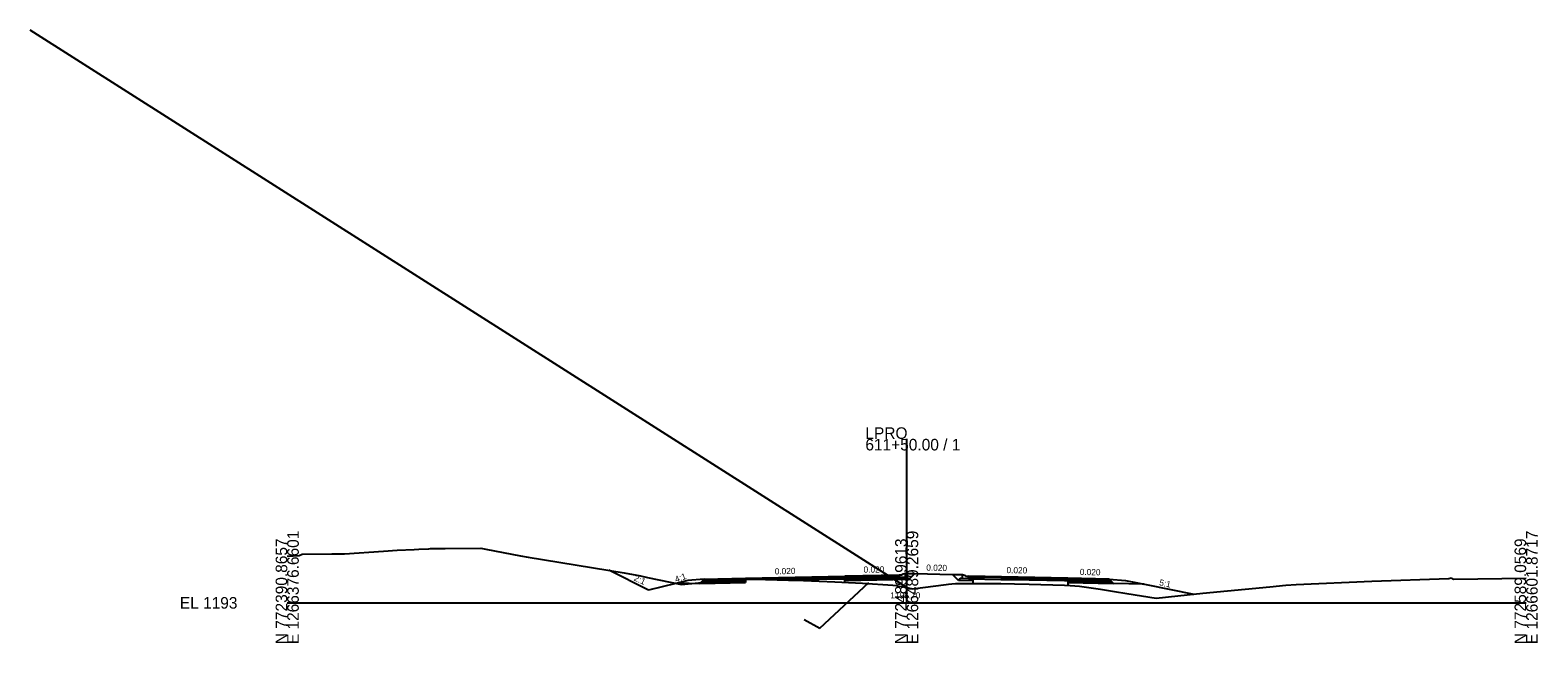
# Model space of a CAD drawing. Extents: x -3833 to 1267678, y -522 to 773248.
# Drawn here: x 1937.8 to 2302.8, y 2490.3 to 2638.8 of the extents above; entities that cross this region are included whole.
import ezdxf

# ---------------------------------------------------------------- set-up
doc = ezdxf.new("R2010")
doc.units = 0
for name, color, linetype in [('Exist Cross Section Cell', 7, 'Continuous'), ('Exist XS Center Line Elevation Label', 7, 'Continuous'), ('Exist XS Ground Line', 7, 'Continuous'), ('Prop CMT DNC', 7, 'Continuous'), ('Prop CMT Pvmt Course 1', 7, 'Continuous'), ('Prop CMT Pvmt Course 2', 7, 'Continuous'), ('Prop CMT Pvmt Course 3', 7, 'Continuous'), ('Prop CMT Pvmt Course 4', 7, 'Continuous'), ('Prop CMT Shld Paved Course 1', 7, 'Continuous'), ('Prop CMT Shld Paved Course 2', 7, 'Continuous'), ('Prop CMT Shld Paved Course 4', 7, 'Continuous'), ('Prop CMT Slope Grass', 7, 'Continuous'), ('Prop CMT Subgrade Earthwork', 7, 'Continuous'), ('Prop Conc Curb and Gutter', 7, 'Continuous'), ('Prop Conc Island Cover', 7, 'Continuous'), ('Prop Corridor Mesh Bottom', 7, 'Continuous'), ('Prop XS Ditch Slope Text', 7, 'Continuous'), ('Prop XS Finish Grade', 7, 'Continuous'), ('Prop XS SE Text', 7, 'Continuous'), ('Scratch_Level_1', 7, 'Continuous'), ('Scratch_Level_5', 7, 'Continuous')]:
    doc.layers.add(name, color=color, linetype=linetype)

msp = doc.modelspace()

# ---------------------------------------------------------------- linework, layer by layer
at = {"layer": 'Exist Cross Section Cell'}
for p, q in [((2150, 2500), (2150, 2539.73)), ((2000, 2500), (2150, 2500)), ((2150, 2500), (2300, 2500))]:
    msp.add_line(p, q, dxfattribs=at)
at = {"layer": 'Exist XS Ground Line'}
for p, q in [((2002.92, 2511.45), (2003.62, 2511.81)), ((2003.62, 2511.81), (2010.82, 2511.85)), ((2010.82, 2511.85), (2013.88, 2511.87)), ((2013.88, 2511.87), (2023.32, 2512.53)), ((2023.32, 2512.53), (2026.61, 2512.75)), ((2026.61, 2512.75), (2030.78, 2512.96)), ((2030.78, 2512.96), (2031.83, 2513.02)), ((2031.83, 2513.02), (2034.29, 2513.11)), ((2034.29, 2513.11), (2034.73, 2513.13)), ((2034.73, 2513.13), (2038.28, 2513.16)), ((2038.28, 2513.16), (2046.88, 2513.24)), ((2046.88, 2513.24), (2048.13, 2513.01)), ((2048.13, 2513.01), (2056.49, 2511.4)), ((2000, 2511.31), (2002.92, 2511.45)), ((2056.49, 2511.4), (2058.36, 2511.03)), ((2058.36, 2511.03), (2081.57, 2507.29)), ((2081.57, 2507.29), (2085.53, 2506.56)), ((2085.53, 2506.56), (2087.21, 2506.18)), ((2087.21, 2506.18), (2095.5, 2504.43)), ((2095.5, 2504.43), (2102.92, 2505.2)), ((2102.92, 2505.2), (2104.7, 2505.4)), ((2104.7, 2505.4), (2105.31, 2505.47)), ((2105.31, 2505.47), (2107.71, 2505.75)), ((2107.71, 2505.75), (2109.45, 2505.74)), ((2109.45, 2505.74), (2113.04, 2505.73)), ((2113.04, 2505.73), (2121.42, 2505.51)), ((2121.42, 2505.51), (2125.01, 2505.4)), ((2125.01, 2505.4), (2132.61, 2505.07)), ((2132.61, 2505.07), (2137.6, 2504.85)), ((2137.6, 2504.85), (2139.32, 2504.75)), ((2139.32, 2504.75), (2146.62, 2504.29)), ((2159.58, 2504.46), (2160.16, 2504.55)), ((2160.16, 2504.55), (2160.92, 2504.64)), ((2160.92, 2504.64), (2161.81, 2504.66)), ((2161.81, 2504.66), (2164.17, 2504.71)), ((2164.17, 2504.71), (2172.78, 2504.66)), ((2172.78, 2504.66), (2176.08, 2504.64)), ((2176.08, 2504.64), (2179.68, 2504.53)), ((2179.68, 2504.53), (2188.19, 2504.3)), ((2244.35, 2504.43), (2262.65, 2505.26)), ((2262.65, 2505.26), (2281.3, 2505.87)), ((2281.3, 2505.87), (2281.87, 2506.07)), ((2281.87, 2506.07), (2282.43, 2505.72)), ((2282.43, 2505.72), (2300, 2505.96)), ((2146.62, 2504.29), (2147.55, 2504.21)), ((2147.55, 2504.21), (2148.14, 2504.08)), ((2148.14, 2504.08), (2148.99, 2503.93)), ((2148.99, 2503.93), (2149.55, 2503.81)), ((2149.55, 2503.81), (2150, 2503.7)), ((2150, 2503.7), (2151.39, 2503.39)), ((2151.39, 2503.39), (2159.58, 2504.46)), ((2188.19, 2504.3), (2189.56, 2504.21)), ((2189.56, 2504.21), (2191.84, 2504.06)), ((2191.84, 2504.06), (2196.92, 2503.28)), ((2196.92, 2503.28), (2200.29, 2502.77)), ((2200.29, 2502.77), (2203.33, 2502.3)), ((2203.33, 2502.3), (2210.39, 2501.13)), ((2210.39, 2501.13), (2215.67, 2501.7)), ((2215.67, 2501.7), (2221.72, 2502.35)), ((2221.72, 2502.35), (2237.95, 2503.89)), ((2237.95, 2503.89), (2241.82, 2504.31)), ((2241.82, 2504.31), (2244.35, 2504.43))]:
    msp.add_line(p, q, dxfattribs=at)
at = {"layer": 'Prop CMT Pvmt Course 1'}
for p, q in [((2111, 2505.95), (2135, 2506.43)), ((2135, 2506.18), (2111, 2505.74)), ((2111, 2505.74), (2111, 2505.95)), ((2111, 2505.95), (2111, 2505.95)), ((2135, 2506.43), (2135, 2506.43)), ((2135, 2506.43), (2135, 2506.43)), ((2135, 2506.43), (2135, 2506.18)), ((2135, 2506.18), (2135, 2506.18)), ((2189, 2505.95), (2165, 2506.43)), ((2165, 2506.43), (2165, 2506.43)), ((2165, 2506.43), (2165, 2506.43)), ((2165, 2506.43), (2165, 2506.18)), ((2165, 2506.18), (2165, 2506.18)), ((2189, 2505.7), (2189, 2505.95)), ((2189, 2505.95), (2189, 2505.95))]:
    msp.add_line(p, q, dxfattribs=at)
at = {"layer": 'Prop CMT Pvmt Course 2'}
for p, q in [((2148.18, 2506.45), (2135, 2506.18)), ((2135, 2506.18), (2135, 2506.18)), ((2135, 2506.18), (2135, 2505.85)), ((2135, 2505.85), (2148.18, 2506.11)), ((2135, 2505.85), (2135, 2505.85)), ((2150, 2506.48), (2150, 2506.48)), ((2150, 2506.48), (2150, 2506.48)), ((2150, 2506.15), (2150, 2506.15)), ((2150, 2506.15), (2150, 2506.15)), ((2165, 2505.85), (2165, 2506.18)), ((2165, 2506.18), (2165, 2506.18)), ((2165, 2505.85), (2165, 2505.85))]:
    msp.add_line(p, q, dxfattribs=at)
at = {"layer": 'Prop CMT Pvmt Course 3'}
for p, q in [((2148.21, 2506.11), (2148.18, 2506.11)), ((2150.19, 2506.15), (2148.21, 2506.11)), ((2150.47, 2505.87), (2150.19, 2506.15)), ((2162.7, 2505.6), (2162.99, 2505.89)), ((2166, 2506.41), (2166, 2505.37))]:
    msp.add_line(p, q, dxfattribs=at)
at = {"layer": 'Prop CMT Pvmt Course 4'}
for p, q in [((2135, 2505.85), (2148.18, 2506.11)), ((2135, 2504.97), (2135, 2505.85)), ((2135, 2505.85), (2135, 2505.85)), ((2135, 2505.85), (2135, 2505.85)), ((2135, 2505.39), (2150.63, 2505.71)), ((2150.19, 2506.15), (2149.69, 2506.14)), ((2150, 2506.15), (2150, 2506.15)), ((2150, 2506.15), (2150, 2506.15)), ((2150.19, 2506.15), (2150.63, 2505.71)), ((2162.99, 2505.89), (2162.54, 2505.44)), ((2163.49, 2505.88), (2162.99, 2505.89)), ((2165, 2505.85), (2165, 2505.85)), ((2165, 2505.85), (2165, 2505.85))]:
    msp.add_line(p, q, dxfattribs=at)
at = {"layer": 'Prop CMT Shld Paved Course 1'}
for p, q in [((2100.74, 2505.5), (2101, 2505.75)), ((2111, 2505.7), (2100.74, 2505.5)), ((2101, 2505.75), (2111, 2505.95)), ((2111, 2505.95), (2111, 2505.7)), ((2148.18, 2506.7), (2135, 2506.43)), ((2135, 2506.18), (2148.18, 2506.45)), ((2135, 2506.43), (2135, 2506.43)), ((2135, 2506.43), (2135, 2506.18)), ((2150, 2506.48), (2150, 2506.48)), ((2150, 2506.48), (2150, 2506.48)), ((2165, 2506.18), (2165, 2506.43)), ((2165, 2506.43), (2165, 2506.43)), ((2189, 2505.95), (2189, 2505.7)), ((2199, 2505.75), (2189, 2505.95)), ((2189, 2505.7), (2199.26, 2505.5)), ((2199.26, 2505.5), (2199, 2505.75))]:
    msp.add_line(p, q, dxfattribs=at)
at = {"layer": 'Prop CMT Shld Paved Course 2'}
for p, q in [((2100.41, 2505.16), (2100.74, 2505.5)), ((2111, 2505.37), (2100.41, 2505.16)), ((2100.74, 2505.5), (2111, 2505.7)), ((2111, 2505.7), (2111, 2505.74)), ((2111, 2505.74), (2112.61, 2505.74)), ((2113.04, 2505.74), (2111, 2505.74)), ((2111, 2505.74), (2111, 2505.7)), ((2111, 2505.7), (2111, 2505.37)), ((2112.61, 2505.74), (2112.61, 2505.74)), ((2112.61, 2505.74), (2112.61, 2505.74)), ((2112.61, 2505.74), (2113.04, 2505.73)), ((2121.42, 2505.91), (2113.04, 2505.74)), ((2113.04, 2505.74), (2113.04, 2505.74)), ((2113.04, 2505.74), (2113.04, 2505.74)), ((2113.04, 2505.73), (2113.04, 2505.73)), ((2113.04, 2505.73), (2119.93, 2505.55)), ((2119.93, 2505.55), (2121.42, 2505.58)), ((2119.93, 2505.55), (2119.93, 2505.55)), ((2125.01, 2505.98), (2121.42, 2505.91)), ((2121.42, 2505.91), (2121.42, 2505.91)), ((2121.42, 2505.58), (2125.01, 2505.65)), ((2121.42, 2505.58), (2121.42, 2505.58)), ((2132.61, 2506.13), (2125.01, 2505.98)), ((2125.01, 2505.98), (2125.01, 2505.98)), ((2125.01, 2505.65), (2132.61, 2505.8)), ((2125.01, 2505.65), (2125.01, 2505.65)), ((2135, 2506.18), (2132.61, 2506.13)), ((2132.61, 2506.13), (2132.61, 2506.13)), ((2132.61, 2505.8), (2135, 2505.85)), ((2132.61, 2505.8), (2132.61, 2505.8)), ((2135, 2505.85), (2135, 2506.18)), ((2135, 2506.18), (2135, 2506.18)), ((2172.78, 2506.03), (2165, 2506.18)), ((2165, 2506.18), (2165, 2506.18)), ((2165, 2506.18), (2165, 2506.18)), ((2165, 2506.18), (2165, 2505.85)), ((2165, 2505.85), (2165, 2505.85)), ((2165, 2505.85), (2172.78, 2505.69)), ((2176.08, 2505.96), (2172.78, 2506.03)), ((2172.78, 2506.03), (2172.78, 2506.03)), ((2172.78, 2505.69), (2172.78, 2505.69)), ((2172.78, 2505.69), (2176.08, 2505.63)), ((2179.68, 2505.89), (2176.08, 2505.96)), ((2176.08, 2505.63), (2179.68, 2505.56)), ((2188.19, 2505.72), (2179.68, 2505.89)), ((2179.68, 2505.89), (2179.68, 2505.89)), ((2179.68, 2505.56), (2179.68, 2505.56)), ((2179.68, 2505.56), (2188.19, 2505.39)), ((2189, 2505.7), (2188.19, 2505.72)), ((2188.19, 2505.72), (2188.19, 2505.72)), ((2188.19, 2505.72), (2188.19, 2505.72)), ((2188.19, 2505.39), (2188.19, 2505.39)), ((2188.19, 2505.39), (2188.19, 2505.39)), ((2188.19, 2505.39), (2189, 2505.37)), ((2189, 2505.37), (2189, 2505.7)), ((2189, 2505.7), (2189, 2505.7)), ((2189, 2505.7), (2189, 2505.7)), ((2189, 2505.7), (2189, 2505.37)), ((2199.26, 2505.5), (2189, 2505.7)), ((2189, 2505.37), (2189, 2505.37)), ((2189, 2505.37), (2199.59, 2505.16)), ((2199.59, 2505.16), (2199.26, 2505.5))]:
    msp.add_line(p, q, dxfattribs=at)
at = {"layer": 'Prop CMT Shld Paved Course 4'}
for p, q in [((2099.94, 2504.69), (2100.41, 2505.16)), ((2111, 2504.91), (2099.94, 2504.69)), ((2100.41, 2505.16), (2100.91, 2505.17)), ((2100.91, 2505.17), (2111, 2505.37)), ((2111, 2505.37), (2111, 2504.91)), ((2189, 2505.37), (2189, 2504.91)), ((2199.09, 2505.17), (2189, 2505.37)), ((2189, 2504.91), (2200.06, 2504.69)), ((2199.59, 2505.16), (2199.09, 2505.17)), ((2200.06, 2504.69), (2199.59, 2505.16))]:
    msp.add_line(p, q, dxfattribs=at)
at = {"layer": 'Prop CMT Slope Grass'}
for p, q in [((2101, 2505.75), (2097, 2505.43)), ((2149.69, 2507.13), (2150.02, 2507.12)), ((2150.02, 2507.12), (2152.01, 2507.08)), ((2161.07, 2506.91), (2163.49, 2506.86)), ((2199, 2505.75), (2203, 2505.43)), ((2203, 2505.43), (2207.44, 2504.55))]:
    msp.add_line(p, q, dxfattribs=at)
at = {"layer": 'Prop CMT Subgrade Earthwork'}
for p, q in [((2094.74, 2504.87), (2099.94, 2504.69)), ((2099.94, 2504.69), (2111, 2504.91)), ((2111, 2504.91), (2111, 2505.74)), ((2150.63, 2505.71), (2135, 2505.39)), ((2135, 2504.97), (2135, 2505.39)), ((2150.63, 2505.71), (2152.01, 2507.08)), ((2162.54, 2505.44), (2161.07, 2506.91)), ((2166, 2505.37), (2162.54, 2505.44)), ((2166, 2505.37), (2166, 2504.7)), ((2200.06, 2504.69), (2189, 2504.91)), ((2189, 2504.91), (2189, 2504.25)), ((2207.44, 2504.55), (2200.06, 2504.69))]:
    msp.add_line(p, q, dxfattribs=at)
at = {"layer": 'Prop Conc Curb and Gutter'}
for p, q in [((2148.18, 2506.7), (2148.18, 2506.7)), ((2148.18, 2506.7), (2148.18, 2506.11)), ((2148.21, 2506.7), (2148.18, 2506.7)), ((2148.18, 2506.11), (2148.21, 2506.11)), ((2148.93, 2506.71), (2148.21, 2506.7)), ((2148.21, 2506.11), (2149.69, 2506.14)), ((2149.69, 2507.13), (2148.93, 2506.88)), ((2148.93, 2506.88), (2148.93, 2506.88)), ((2148.93, 2506.88), (2148.93, 2506.71)), ((2148.93, 2506.71), (2148.93, 2506.71)), ((2149.69, 2506.15), (2149.69, 2507.13)), ((2149.69, 2506.14), (2149.69, 2506.15)), ((2163.49, 2505.88), (2163.49, 2506.86)), ((2163.49, 2506.86), (2163.49, 2506.86)), ((2163.49, 2506.86), (2163.49, 2506.86)), ((2163.49, 2506.86), (2164.25, 2506.61)), ((2165, 2505.85), (2163.49, 2505.88)), ((2163.49, 2505.88), (2163.49, 2505.88)), ((2164.25, 2506.61), (2164.25, 2506.61)), ((2164.25, 2506.61), (2164.25, 2506.45)), ((2164.25, 2506.45), (2165, 2506.43)), ((2164.25, 2506.45), (2164.25, 2506.45)), ((2165, 2506.43), (2165, 2506.43)), ((2165, 2506.43), (2165, 2505.85))]:
    msp.add_line(p, q, dxfattribs=at)
at = {"layer": 'Prop Conc Island Cover'}
for p, q in [((2149.69, 2507.13), (2149.69, 2506.88)), ((2163.49, 2506.86), (2163.49, 2506.86)), ((2163.49, 2506.86), (2163.49, 2506.86)), ((2163.49, 2506.61), (2163.49, 2506.61)), ((2163.49, 2506.61), (2163.49, 2506.61))]:
    msp.add_line(p, q, dxfattribs=at)
at = {"layer": 'Prop Corridor Mesh Bottom'}
for p, q in [((2111, 2505.95), (2111, 2505.7)), ((2135, 2506.43), (2135, 2506.18)), ((2165, 2506.43), (2165, 2506.18)), ((2189, 2505.95), (2189, 2505.7))]:
    msp.add_line(p, q, dxfattribs=at)
at = {"layer": 'Prop XS Finish Grade'}
for p, q in [((2087.5, 2503.06), (2077.84, 2507.89)), ((2094.14, 2504.72), (2087.5, 2503.06)), ((2097, 2505.43), (2094.14, 2504.72)), ((2152.01, 2507.08), (2161.07, 2506.91)), ((2163.49, 2506.86), (2163.49, 2506.86))]:
    msp.add_line(p, q, dxfattribs=at)
msp.add_lwpolyline([(2203, 2505.43), (2208, 2504.43), (2219.57, 2502.12)], dxfattribs=at)
at = {"layer": 'Scratch_Level_1'}
msp.add_line((2150, 2503.7), (1937.75, 2638.76), dxfattribs=at)
at = {"layer": 'Scratch_Level_5'}
for p, q in [((2128.96, 2493.9), (2140.82, 2504.92)), ((2125.18, 2496), (2128.96, 2493.9))]:
    msp.add_line(p, q, dxfattribs=at)

# ---------------------------------------------------------------- texts
at = {"layer": 'Exist Cross Section Cell'}
for s, p in [('LPRO', (2140, 2539.73)), ('611+50.00 / 1', (2140, 2536.93)), ('EL 1193', (1974, 2498.6))]:
    msp.add_text(s, height=2.8, dxfattribs=at).set_placement(p)
for s, p in [('E 1266376.6601', (2002.8, 2490)), ('E 1266489.2659', (2152.8, 2490)), ('E 1266601.8717', (2302.8, 2490)), ('N 772390.8657', (2000, 2490)), ('N 772489.9613', (2150, 2490)), ('N 772589.0569', (2300, 2490))]:
    msp.add_text(s, height=2.8, rotation=90, dxfattribs=at).set_placement(p)
at = {"layer": 'Exist XS Center Line Elevation Label'}
msp.add_text('1196.70', height=1.5, dxfattribs=at).set_placement((2146.04, 2501.06))
at = {"layer": 'Prop CMT DNC'}
for p in [(2111, 2505.95), (2111, 2505.95), (2135, 2506.43), (2135, 2506.43), (2148.93, 2506.71), (2164.25, 2506.45), (2165, 2506.43), (2165, 2506.43), (2189, 2505.95), (2189, 2505.95), (2199, 2505.75)]:
    msp.add_text('X', height=0.00025, dxfattribs=at).set_placement(p)
at = {"layer": 'Prop XS Ditch Slope Text'}
for s, rotation, p in [('2:1', 335.1076, (2083.82, 2505.5)), ('4:1', 19.4296, (2094.16, 2504.91)), ('5:1', 347.5411, (2211.06, 2504.27))]:
    msp.add_text(s, height=1.5, rotation=rotation, dxfattribs=at).set_placement(p)
at = {"layer": 'Prop XS SE Text'}
for rotation, p in [(1.397, (2118.07, 2506.88)), (0.2693, (2139.57, 2507.32)), (358.8542, (2154.74, 2507.8)), (358.8542, (2174.16, 2507.21)), (358.8542, (2191.91, 2506.75))]:
    msp.add_text('0.020', height=1.5, rotation=rotation, dxfattribs=at).set_placement(p)

doc.saveas('drawing.dxf')
